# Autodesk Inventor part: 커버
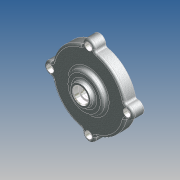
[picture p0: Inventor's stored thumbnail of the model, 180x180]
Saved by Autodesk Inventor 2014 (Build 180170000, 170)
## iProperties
Created: 2012-05
Part Number: 커버
Document SubType Name: 모델링
Designer: SeoGD™
Material: 알루미늄 6061
Appearance: 알루미늄 캐스트
Density: 1 g/cm^3
변환 표준: STEP AP214IS
파일 이름: C:\Users\SeoGD\Desktop\?쒗뿕\而ㅻ쾭-1.stp
전처리기: Build: 253, Release: 2010 SP1 - Date: Wed 07/29/2009
전송 단위: 밀리미터
불확실성: 0.01
Author: SeoGD™
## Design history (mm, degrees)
sketch "스케치1"
  geometry: L1 (0, 0)-(0, 26); L2 (50, 0)-(50, 15); L3 (50, 15)-(25, 15); L4 (25, 15)-(25, 21); L5 (25, 21)-(15, 21); L6 (15, 21)-(13.66, 26); L7 (13.66, 26)-(10, 26); L8 (50, 0)-(45, 0); L9 (45, 0)-(45, 10); L10 (45, 10)-(14.5, 10); L11 (14.5, 10)-(13.266, 3); L12 (13.266, 3)-(11, 3); L13 (11, 3)-(11, 16); L14 (11, 16)-(7.5, 16); L15 (7.5, 16)-(7.5, 19); L16 (7.5, 19)-(10, 19); L17 (10, 19)-(10, 26)
  constraints: 34 end point, 10 parallel, 2 perpendicular, 2 point on line, 1 vertical
  dimensions: "d11" = 100 diameter of L2 L1; "d12" = 22 diameter of L13 L1; "d13" = 90 diameter of L9 L1; "d14" = 15 distance between parallel lines of L3 L8; "d15" = 10 distance between parallel lines of L8 L10; "d16" = 29 diameter of L10.end L1; "d17" = 100 deg angle of L11 L10; "d18" = 7 distance between parallel lines of L12 L10; "d19" = 13 distance between parallel lines of L14 L12; "d20" = 3 distance between parallel lines of L16 L14; "d21" = 15 diameter of L15 L1; "d22" = 20 diameter of L17 L1; "d23" = 30 diameter of L5.end L1; "d24" = 6 distance between parallel lines of L5 L3; "d25" = 50 diameter of L4 L1; "d26" = 105 deg angle of L5 L6; "d50" = 26 distance of L1.start L1.end
revolve "회전1" sketch "스케치1" stored, may be unused: angle "d27" = 90 deg
sketch "스케치2" dims "d29" = 104
  geometry: A1 r 8.5 centre (0, 52) between (8.074, 49.344) and (-8.074, 49.344); A2 r 50 centre (0, 0) between (-8.074, 49.344) and (8.074, 49.344) reference; 2 further points
  constraints: 4 point on circle, 2 vertical alignment, 1 centre point, 1 coincident, 2 other
  dimensions: "d28" = 17 diameter of A1
extrude "돌출1" join sketch "스케치2" stored distance "d30" = 10; taper "d31" = 0 deg
fillet "모깎기3" dims "d32" = 3
fillet "모깎기4" dims "d45" = 3, "d46" = 0.2
chamfer "모따기1" distance "d47" = 1; stored, may be unused: second distance "d48" = 2, angle "d49" = 45 deg
hole "구멍2" diameter "d38" = 5.5; stored, may be unused: countersink angle "d42" = 90 deg, drill point angle "d44" = 118 deg; dims "d36" = 10, "d37" = 10, "d39" = 6, "d40" = 9.5, "d41" = 5.4, "d43" = 8
node "솔리드1"
node "솔리드 본체"
node "곡면 본체"
pattern_circular "원형 패턴1" dims angle "d34" = 360 deg
pattern_circular "원형 패턴2" dims angle "d52" = 360 deg
node "솔리드2"
